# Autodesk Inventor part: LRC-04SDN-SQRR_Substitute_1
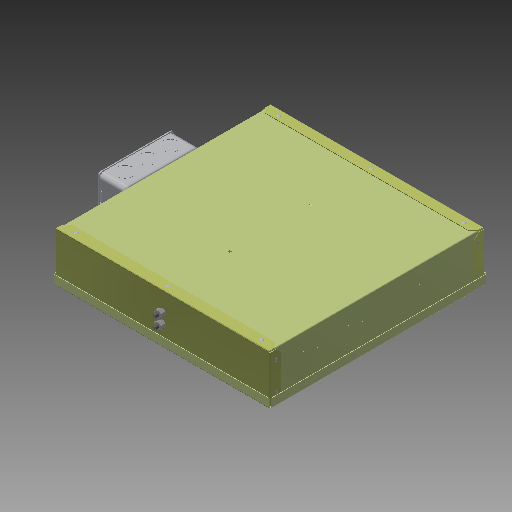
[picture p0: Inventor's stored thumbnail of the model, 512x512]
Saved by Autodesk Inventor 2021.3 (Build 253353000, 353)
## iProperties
Part Number: LRC-04SDN-SQRR_Substitute_1
Material: Generic
Document SubType Name: Modeling
Designer: JChurch
Manufacturer: Standard
Standards Organization: Custom
Density: 1 g/cm^3
Appearance: Smooth - Black
Mass: 945.366 g
Surface Area: 7818.6 cm^2
Volume: 397.379 cm^3
Author: JChurch
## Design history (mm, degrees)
derived "LRC-04SDN-SQRR.iam"
body "Solid9"
node "830557-00-00.iam:1::830557-PAN.ipt:1"
node "830557-00-00.iam:1::830557-FLANGE.ipt:2"
body "Solid10"
node "830557-00-00.iam:1::506010-00-38 SQUEEZED.ipt:1"
body "Solid11"
node "830557-00-00.iam:1::506010-00-38 SQUEEZED.ipt:2"
body "Solid12"
node "830557-00-00.iam:1::506010-00-38 SQUEEZED.ipt:3"
body "Solid13"
node "830557-00-00.iam:1::506010-00-38 SQUEEZED.ipt:4"
body "Solid14"
node "830557-00-00.iam:1::506010-00-38 SQUEEZED.ipt:5"
body "Solid15"
node "830557-00-00.iam:1::506010-00-38 SQUEEZED.ipt:6"
body "Solid16"
node "830557-00-00.iam:1::506010-00-38 SQUEEZED.ipt:7"
body "Solid17"
node "830557-00-00.iam:1::506010-00-38 SQUEEZED.ipt:8"
body "Solid18"
node "830557-00-00.iam:1::830557-FLANGE.ipt:3"
body "Solid19"
node "885000-00-00.iam:1::830000-00-00.ipt:1"
body "Solid20"
node "885000-00-00.iam:1::509424-00-00.ipt:1"
body "Solid21"
node "885000-00-00.iam:1::830593-00-00.ipt:1"
body "Solid22"
node "885000-00-00.iam:1::506002-00-00.ipt:1"
body "Solid23"
node "885000-00-00.iam:1::506002-00-00.ipt:2"
body "Solid24"
node "885000-00-00.iam:1::506002-00-00.ipt:3"
body "Solid25"
node "885000-00-00.iam:1::506002-00-00.ipt:4"
body "Solid26"
node "885000-00-00.iam:1::506002-00-00.ipt:5"
body "Solid27"
node "885000-00-00.iam:1::506002-00-00.ipt:6"
body "Solid28"
node "885000-00-00.iam:1::506002-00-00.ipt:7"
body "Solid29"
node "885000-00-00.iam:1::506002-00-00.ipt:8"
body "Solid30"
node "885000-00-00.iam:1::506002-00-00.ipt:9"
body "Solid31"
node "885000-00-00.iam:1::506002-00-00.ipt:10"
body "Solid32"
node "885000-00-00.iam:1::506002-00-00.ipt:11"
body "Solid33"
node "885000-00-00.iam:1::506002-00-00.ipt:12"
body "Solid34"
node "885000-00-00.iam:1::506002-00-00.ipt:13"
body "Solid35"
node "885000-00-00.iam:1::506002-00-00.ipt:14"
body "Solid36"
node "885000-00-00.iam:1::500027-00-00.ipt:1"
body "Solid37"
node "885000-00-00.iam:1::500027-00-00.ipt:2"
body "Solid38"
node "885000-00-00.iam:1::502116-00-00.ipt:1"
body "Solid39"
node "885000-00-00.iam:1::502116-00-00.ipt:2"
body "Solid40"
node "885000-00-00.iam:1::501030-00-00.ipt:1"
body "Solid41"
node "885000-00-00.iam:1::501030-00-00.ipt:2"
body "Solid42"
node "885000-00-00.iam:1::501030-00-00.ipt:3"
body "Solid43"
node "885000-00-00.iam:1::501030-00-00.ipt:4"
body "Solid44"
node "885000-00-00.iam:1::500027-00-00.ipt:3"
body "Solid45"
node "885000-00-00.iam:1::500027-00-00.ipt:4"
body "Solid46"
node "885000-00-00.iam:1::501030-00-00.ipt:5"
body "Solid47"
node "885000-00-00.iam:1::500027-00-00.ipt:5"
body "Solid48"
node "885000-00-00.iam:1::501030-00-00.ipt:6"
body "Solid49"
node "885000-00-00.iam:1::500027-00-00.ipt:6"
body "Solid50"
node "885000-00-00.iam:1::830593-00-00.ipt:2"
body "Solid51"
node "885000-00-00.iam:1::507032-00-00.ipt:1"
body "Solid52"
node "885000-00-00.iam:1::640042-00-03.ipt:1"
body "Solid53"
node "885000-00-00.iam:1::501030-00-00.ipt:9"
body "Solid54"
node "885000-00-00.iam:1::501030-00-00.ipt:10"
body "Solid55"
node "885000-00-00.iam:1::501030-00-00.ipt:11"
body "Solid56"
node "885000-00-00.iam:1::501030-00-00.ipt:12"
body "Solid57"
node "885000-00-00.iam:1::503031-00-00.ipt:1"
body "Solid58"
node "885000-00-00.iam:1::503031-00-00.ipt:2"
body "Solid59"
node "885000-00-00.iam:1::509425-00-00.ipt:1"
body "Solid60"
node "750206-00-00.iam:1::740066-00-XX.iam:1::840076-00-00_5.75.ip"
body "Solid61"
node "750206-00-00.iam:1::740066-00-XX.iam:1::840076-00-00_5.75.ip"
body "Solid62"
node "750206-00-00.iam:1::740066-00-XX.iam:1::840076-00-00_5.75.ip"
body "Solid63"
node "750206-00-00.iam:1::740066-00-XX.iam:1::840076-00-00_5.75.ip"
body "Solid64"
node "750206-00-00.iam:1::507055-00-38.ipt:1"
body "Solid65"
node "750206-00-00.iam:1::507055-00-38.ipt:2"
body "Solid66"
node "725292-00-00.ipt:1"
body "Solid67"
other parameters: "d15" = 61.595, "d16" = 9.525, "d17" = 9.525, "d35" = 5.08
